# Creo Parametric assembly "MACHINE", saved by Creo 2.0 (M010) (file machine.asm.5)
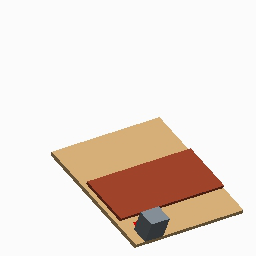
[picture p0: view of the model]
Units: Inch lbm Second (Pro/E Default); INCH, POUND, SECS

Created from: INLBS_ASM_DESIGN.ASM

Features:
  1. datum plane "ASM_RIGHT"
  2. datum plane "ASM_TOP"
  3. datum plane "ASM_FRONT"
  4. coordinate system
  5. component "BASE_BOARD"
  6. component "TOPBOARD"
  7. component "YMOTOR"
  8. component "MOTOR"

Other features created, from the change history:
  component "YMOTOR.PRT"
  component "BASE_BOARD.PRT"
  component "TOPBOARD.PRT"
